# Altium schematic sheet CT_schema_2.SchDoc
size 276 x 169 mm
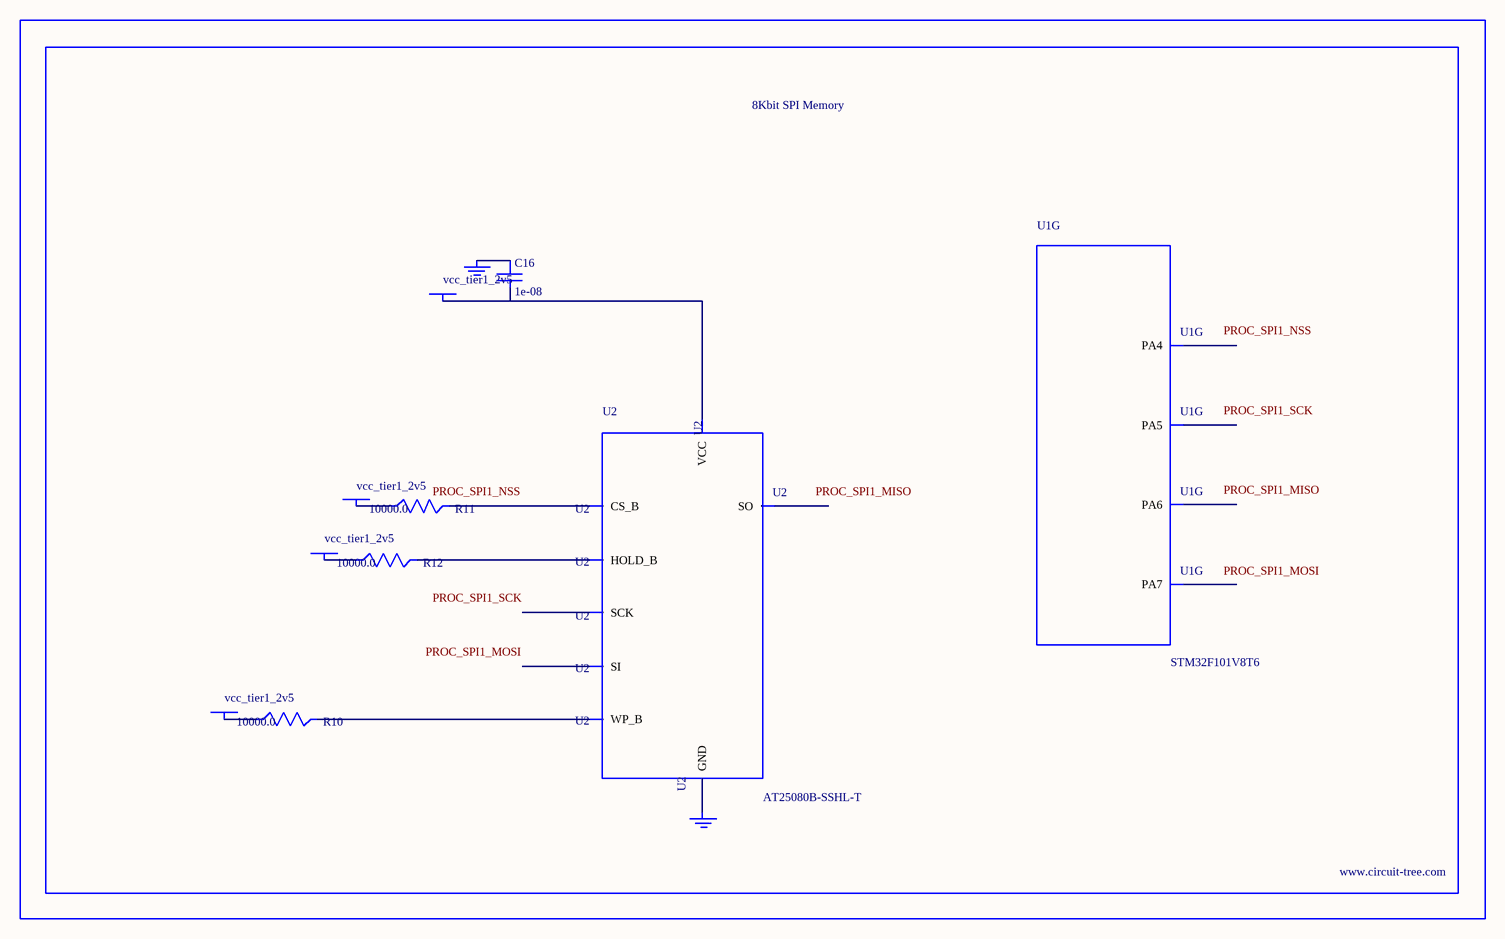
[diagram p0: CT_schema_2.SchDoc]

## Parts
BORDER1  (no value)
C16  1e-08  [C0402]
GND_INSTANCE_1_0  (no value)
GND_INSTANCE_1_1  (no value)
POWER_INSTANCE_1_0  vcc_tier1_2v5
POWER_INSTANCE_1_1  vcc_tier1_2v5
POWER_INSTANCE_1_2  vcc_tier1_2v5
POWER_INSTANCE_1_3  vcc_tier1_2v5
R10  10000.0  [R0603]
R11  10000.0  [R0603]
R12  10000.0  [R0603]
U1  STM32F101V8T6  [LQFP100]  (part G of 10)
U2  AT25080B-SSHL-T  [SOIC-8]

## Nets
NetC16_1: C16.1 GND_INSTANCE_1_0.0(GND)
NetC16_2: C16.2 POWER_INSTANCE_1_3.0(PWR) U2.8(VCC)
NetGND_INSTANCE_1_1_0: GND_INSTANCE_1_1.0(GND) U2.4(GND)
NetPOWER_INSTANCE_1_0_0: POWER_INSTANCE_1_0.0(PWR) R11.1
NetPOWER_INSTANCE_1_1_0: POWER_INSTANCE_1_1.0(PWR) R10.1
NetPOWER_INSTANCE_1_2_0: POWER_INSTANCE_1_2.0(PWR) R12.1
NetR10_2: R10.2 U2.3(WP_B)
NetR11_2: R11.2 U2.1(CS_B)
NetR12_2: R12.2 U2.7(HOLD_B)

Not connected (* = marked no-connect by the designer): U1 29(PA4) 30(PA5) 31(PA6) 32(PA7); U2 2(SO) 5(SI) 6(SCK)

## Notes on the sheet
- Labels drawn without touching a wire or pin: PROC_SPI1_MISO, PROC_SPI1_MOSI, PROC_SPI1_NSS, PROC_SPI1_SCK

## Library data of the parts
BORDER1 = BORDER_PAGE1
C16 = C0402C103K3RAC
GND_INSTANCE_1_0 GND_INSTANCE_1_1 = GND
POWER_INSTANCE_1_0-POWER_INSTANCE_1_3 = PWR
R10-R12 = RC0603JR-0710KL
